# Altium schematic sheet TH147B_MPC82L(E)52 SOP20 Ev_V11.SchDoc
size 279 x 193 mm; PageSetup: Record=PageOptions|CenterHorizontal=True|CenterVertical=True|PrintScale=1.02|XCorrection=1.00|YCorrection=1.00|PrintKind=0|BorderSize=5000000|LeftOffset=0|BottomOffset=0|Orientation=2|PaperLength=1000|PaperWidth=1000|Scale=100|PaperSource=7|PrintQuality=-4|MediaType=1|DitherType=10|PaperKind=A4 (210 x 297 mm)|PrintScaleMode=1
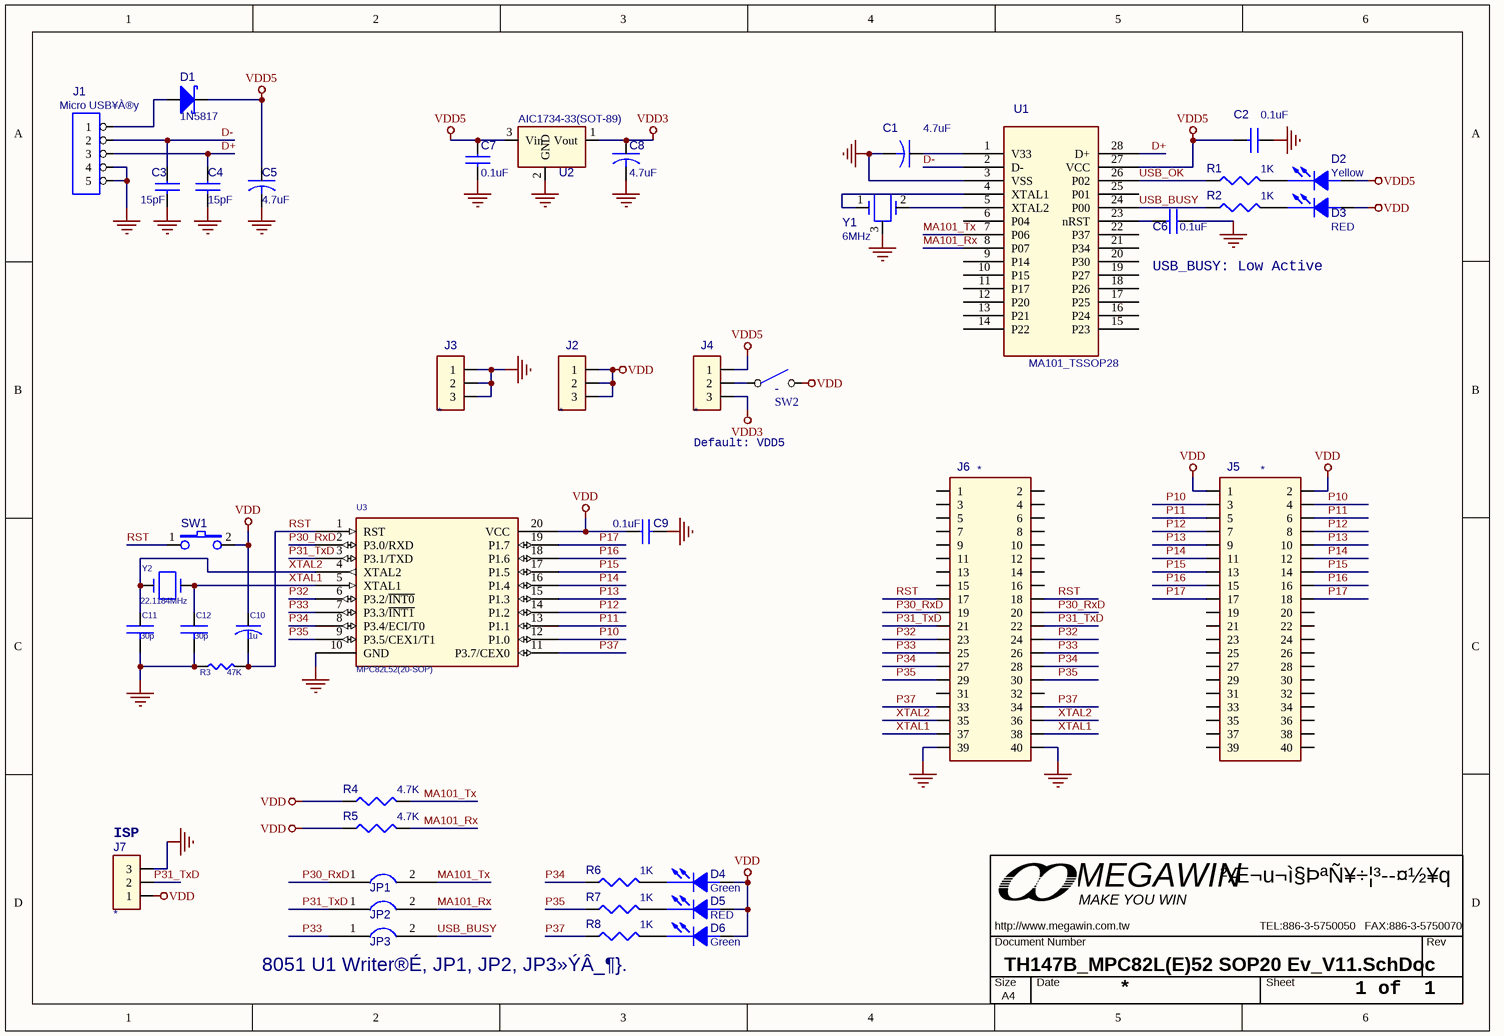
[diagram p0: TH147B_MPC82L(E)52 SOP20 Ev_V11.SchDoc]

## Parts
C1  4.7uF  [0805C]
C2  0.1uF  [0805C]
C3  15pF  [0805C]
C4  15pF  [0805C]
C5  4.7uF  [1206C]
C6  0.1uF  [0805C]
C7  0.1uF  [0805C]
C8  4.7uF  [0805C]
C9  0.1uF  [0805C]
C10  1u  [0805C]
C11  30p  [0805C]
C12  30p  [0805C]
D1  1N5817  [D5817_SMD_1]
D2  Yellow  [0805D]
D3  RED  [0805D]
D4  Green  [0805D]
D5  RED  [0805D]
D6  Green  [0805D]
J1  Micro USB¥À®y  [JACK_USB_SMD290X220P065]
J2  *  [PS3P254]
J3  *  [PS3P254]
J4  *  [JUMP3_SMD]
J5  *  [PS20X2P254]
J6  *  [PS20X2P254]
J7  *  [PS3P254f_90]
JP1  JUMPER2  [PS2P254]  (value not drawn)
JP2  JUMPER2  [PS2P254]  (value not drawn)
JP3  JUMPER2  [PS2P254]  (value not drawn)
MW1  OrgName: ²Æ¬u¬ì§ÞªÑ¥÷¦³­­¤½¥q  OrgAddr1: MEGAWIN  OrgAddr3: TEL:886-3-5750050   FAX:886-3-5750070  Page Size: A4  [MEGAWIN_T]  (hidden comment: MW-A4)  (no BOM)
R1  1K  [0805R]
R2  1K  [0805R]
R3  47K  [0805R]
R4  4.7K  [0805R]
R5  4.7K  [0805R]
R6  1K  [0805R]
R7  1K  [0805R]
R8  1K  [0805R]
SW1  SW TACT-SPST  [SW_T_2P]  (value not drawn)
SW2  -  [DIP2_SW]
U1  MA101_TSSOP28  [TSSOP28_170P065]
U2  AIC1734-33(SOT-89)  [SOT89]
U3  MPC82L52(20-SOP)  [SO20_300P127]
Y1  6MHz  [X3P]
Y2  22.1184MHz  [X49U]

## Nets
GND_POWER: C1.2 C2.1 C3.2 C4.2 C5.2 C6.1 C7.2 C8.2 C9.2 C11.2 C12.2 J1.4 J1.5 J3.1 J3.2 J3.3 J6.39 J6.40 J7.3 R3.1 U1.3(VSS) U2.2(GND) U3.10(GND) Y1.3
VDD: C9.1 C10.1(POS) D3.1(ANODE) D4.1(ANODE) D5.1(ANODE) D6.1(ANODE) J2.1 J2.2 J2.3 J5.1 J5.2 J7.1 R4.1 R5.1 SW1.2 SW2.2(NO) U3.20(VCC)
VDD3: C8.1 J4.3 U2.1(Vout)
VDD5: C2.2 C5.1 C7.1 D1.2(K) D2.1(ANODE) J4.1 U1.27(VCC) U2.3(Vin)
D+: C4.1 J1.3 U1.28(D+)
D-: C3.1 J1.2 U1.2(D-)
MA101_Rx: JP2.2 R5.2 U1.8(P07)
MA101_Tx: JP1.2 R4.2 U1.7(P06)
P10: J5.3 J5.4 U3.12(P1.0)
P11: J5.5 J5.6 U3.13(P1.1)
P12: J5.7 J5.8 U3.14(P1.2)
P13: J5.9 J5.10 U3.15(P1.3)
P14: J5.11 J5.12 U3.16(P1.4)
P15: J5.13 J5.14 U3.17(P1.5)
P16: J5.15 J5.16 U3.18(P1.6)
P17: J5.17 J5.18 U3.19(P1.7)
P30_RxD: J6.19 J6.20 JP1.1 U3.2(P3.0/RXD)
P31_TxD: J6.21 J6.22 J7.2 JP2.1 U3.3(P3.1/TXD)
P32: J6.23 J6.24 U3.6(P3.2/~{INT0})
P33: J6.25 J6.26 JP3.1 U3.7(P3.3/~{INT1})
P34: J6.27 J6.28 R6.1 U3.8(P3.4/ECI/T0)
P35: J6.29 J6.30 R7.1 U3.9(P3.5/CEX1/T1)
P37: J6.33 J6.34 R8.1 U3.11(P3.7/CEX0)
RST: C10.2(NEG) J6.17 J6.18 R3.2 SW1.1 U3.1(RST)
USB_BUSY: JP3.2 R2.1 U1.24(P00)
USB_OK: R1.1 U1.26(P02)
XTAL1: C12.1 J6.37 J6.38 U3.5(XTAL1) Y2.2
XTAL2: C11.1 J6.35 J6.36 U3.4(XTAL2) Y2.1
NetC1_1: C1.1 U1.1(V33)
NetC6_2: C6.2 U1.23(nRST)
NetD1_1: D1.1(A) J1.1
NetD2_2: D2.2(CATHODE) R1.2
NetD3_2: D3.2(CATHODE) R2.2
NetD4_2: D4.2(CATHODE) R6.2
NetD5_2: D5.2(CATHODE) R7.2
NetD6_2: D6.2(CATHODE) R8.2
NetJ4_2: J4.2 SW2.1(COMMON)
NetU1_4: U1.4(XTAL1) Y1.1
NetU1_5: U1.5(XTAL2) Y1.2

Not connected (* = marked no-connect by the designer): J5 19 20 21 22 23 24 25 26 27 28 29 30 31 32 33 34 35 36 37 38 39 40; J6 1 2 3 4 5 6 7 8 9 10 11 12 13 14 15 16 31 32; U1 6(P04) 9(P14) 10(P15) 11(P17) 12(P20) 13(P21) 14(P22) 15(P23) 16(P24) 17(P25) 18(P26) 19(P27) 20(P30) 21(P34) 22(P37) 25(P01)

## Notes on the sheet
- USB_BUSY: Low Active
- Default: VDD5
- (near J7) ISP
- 8051 U1 Writer®É, JP1, JP2, JP3»ÝÂ_¶}.
- 1 of  1

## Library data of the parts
C1 C5 C8 = CAP
C2-C4 C6 C7 C9 = CAP NP
C10 = C
C11 C12 = C NP
D1 = DIODE_ZD: Schottky Diode
D2-D6 = LED
J1 = CON5: Connector
J2-J4 J7 = CON3
J5 J6 = CON40A
R1 R2 R4-R8 = R_Dup1
R3 = R
SW2 = SW-2
U2 = AIC1734-33(SOT-89)_0
U3 = MPC82L52(20-DIP)
Y1 = CRYSTAL_RC
Y2 = CRYSTAL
